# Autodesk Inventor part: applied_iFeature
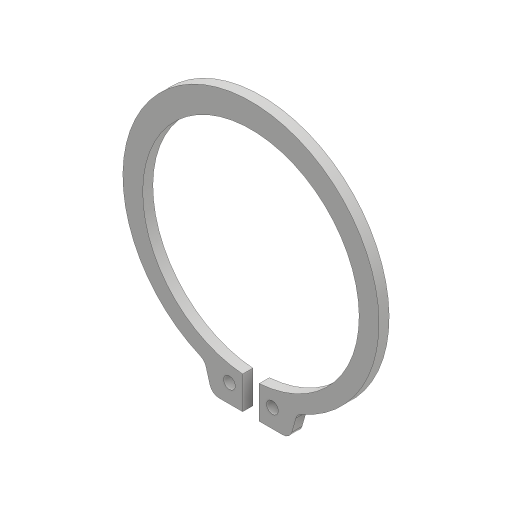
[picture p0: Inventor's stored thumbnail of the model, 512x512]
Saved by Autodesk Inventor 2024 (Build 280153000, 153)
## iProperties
Created: 2016-06
Part Number: applied_iFeature
Material: Generic
Document SubType Name: Modeling
Designer: CADCIM
Density: 1 g/cm^3
Appearance: Default
Author: CADCIM
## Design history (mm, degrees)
sketch "Sketch1"
  geometry: L1 (9.52, -25.305)-(8.665, -28.284); L2 (6.743, -29.733)-(1.75, -29.733); L3 (1.75, -29.733)-(1.75, -22.833); L4 (0, 0)-(0, -33.55); L5 (-6.743, -29.733)-(-1.75, -29.733); L6 (-1.75, -29.733)-(-1.75, -22.833); L7 (-9.52, -25.305)-(-8.665, -28.284); C1 r 1.25 at (4.55, -25.815); C2 r 1.25 at (-4.55, -25.815); A1 r 22.9 centre (0, 0) between (1.75, -22.833) and (-1.75, -22.833); A2 r 27.1 centre (0, 0.9) between (10.656, -24.017) and (-10.656, -24.017); A3 r 2 centre (-6.743, -27.733) between (-8.665, -28.284) and (-6.743, -29.733); A4 r 2 centre (-11.442, -25.856) between (-9.52, -25.305) and (-10.656, -24.017); A5 r 2 centre (11.442, -25.856) between (10.656, -24.017) and (9.52, -25.305); A6 r 2 centre (6.743, -27.733) between (6.743, -29.733) and (8.665, -28.284); 12 further points
  constraints: 18 point on circle, 14 end point, 8 centre point, 8 point on line, 8 tangent, 4 equal radius, 4 symmetric about line, 2 coincident, 2 midpoint, 1 horizontal, 1 horizontal alignment, 1 perpendicular, 1 vertical
  dimensions: "d0" = 45.8 diameter of A1; "d4" = 6.9 distance from line of L6.end L5; "d5" = 5.1 distance of point (0, 28) point (0, 22.9); "d6" = 2.5 diameter of C1; "d8" = 2 radius of A3 (derived); "d9" = 2.8 distance from line of C1.centre L3; "d10" = 3.5 distance of L5.end L2.end; "d11" = 27.1 radius of A2; "d14" = 6.5 distance of L5.end point (-8.25, -29.733); "d15" = 32 deg angle of L7 L1
extrude "Extrusion1" new body sketch "Sketch1" distance "d16" = 2.15; taper "d17" = 0 deg
body "Solid1"
